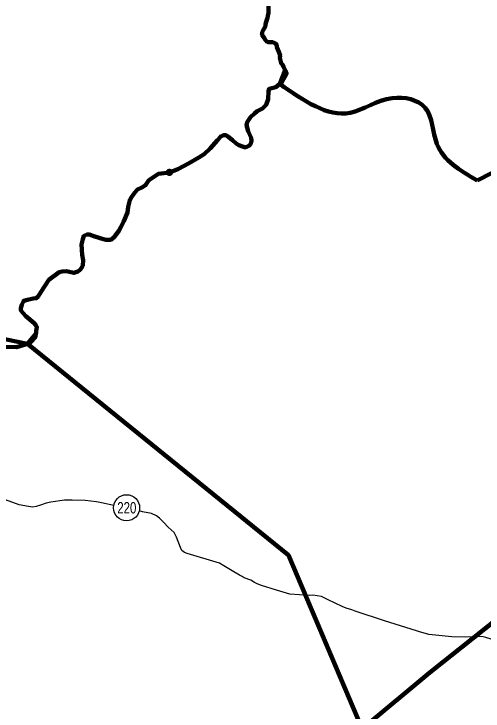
# Model space of a CAD drawing. Extents: x 553962 to 842807, y 8883888 to 9032388.
# Drawn here: x 729677 to 744097, y 8923744 to 8945147 of the extents above; entities that cross this region are included whole.
import ezdxf
from ezdxf.enums import TextEntityAlignment as Align

# ---------------------------------------------------------------- set-up
doc = ezdxf.new("R2010")
doc.units = 0
doc.header["$LTSCALE"] = 200
doc.header["$PDMODE"] = 32
doc.header["$PDSIZE"] = 100
for name, color, linetype, lineweight in [('12', 7, 'Continuous', 25), ('24', 7, 'Continuous', 25), ('48', 7, 'Continuous', 25), ('9', 7, 'Continuous', 90)]:
    doc.layers.add(name, color=color, linetype=linetype, lineweight=lineweight)

msp = doc.modelspace()

# ---------------------------------------------------------------- linework, layer by layer
at = {"layer": '12'}
msp.add_line((742048.5, 8926210.1), (741071.5, 8926510.4), dxfattribs=at)
for points in [[(730249.8, 8930002.8), (730122.6, 8930028.5), (729842.6, 8930080), (728682.6, 8930494.7)], [(732746.1, 8930058.5), (732369.6, 8930141.5), (732211.8, 8930172.4), (731870.6, 8930203.6), (731463.1, 8930219.6), (731228.7, 8930220), (730810.8, 8930159.7), (730662.9, 8930124.3), (730494.6, 8930063.5), (730356.9, 8930023), (730249.8, 8930002.8)], [(741071.5, 8926510.4), (740161.8, 8926805.8), (740060.1, 8926851.9), (739892.2, 8926903.1), (739765, 8926949.2), (739337.8, 8927153.8), (739129.4, 8927261.1), (738864.6, 8927302.4), (738747.4, 8927287.3), (738156.6, 8927334.2), (737744.4, 8927452.2), (737286.5, 8927600.7), (737149.1, 8927646.8), (737067.7, 8927687.7), (736955.9, 8927764.3), (736752.4, 8927830.9), (736696.5, 8927876.9), (736610.1, 8927912.7), (736386.4, 8928050.7), (736127.2, 8928198.9), (736000.1, 8928285.7), (735002.7, 8928577.9), (734921.3, 8928613.7), (734840, 8928669.9), (734799.6, 8928766.8), (734673.4, 8929087.9), (734602.6, 8929225.6), (734419.8, 8929388.9), (734272.7, 8929542), (734150.8, 8929664.5), (734054.3, 8929736), (733901.8, 8929807.6), (733626.9, 8929864.1), (733521.6, 8929887.4)], [(745369.8, 8925577.3), (745323, 8925594.1), (744341.2, 8925952.5), (744183.4, 8925998.7), (744096.9, 8926019.2), (743954.3, 8926029.7), (743572.1, 8926010), (743134, 8926021), (742629.9, 8926077.9), (742426.2, 8926098.7), (742115.8, 8926185.9), (742048.5, 8926210.1)]]:
    msp.add_lwpolyline(points, dxfattribs=at)
at = {"layer": '24', "lineweight": 53}
for points in [[(737354.5, 8945706.8), (737394.5, 8945630.5), (737439.8, 8945559), (737475, 8945507.8), (737499.8, 8945416), (737504.6, 8945365.1), (737504, 8945288.7), (737498.2, 8945176.7), (737482.3, 8945090.2), (737466.6, 8945029.2), (737445.8, 8944963.1), (737430.2, 8944902.1), (737414.4, 8944830.9), (737408.9, 8944774.9), (737372.8, 8944698.8), (737342, 8944653.1), (737311, 8944587.1), (737305.5, 8944531.1), (737295.3, 8944521), (737294.5, 8944512.4)], [(737294.5, 8944512.4), (737310.4, 8944496.3), (737340.7, 8944455.3), (737370.9, 8944409.3), (737411.1, 8944342.9), (737446.4, 8944296.8), (737492, 8944276.2), (737558.2, 8944280.9), (737634.4, 8944280.4), (737715.5, 8944239.2), (737755.9, 8944193.1), (737760.6, 8944132), (737785.4, 8944050.3), (737815.4, 8943978.8), (737855.4, 8943871.7), (737854.9, 8943800.4), (737869.6, 8943718.8), (737889.3, 8943632.1), (737934.8, 8943591.1), (737964.9, 8943524.7), (738014.8, 8943418.8), (738014.7, 8943418.2), (738014.8, 8943418.8)], [(738014.8, 8943418.8), (738029.4, 8943395.5), (738053.2, 8943344.5), (738056.5, 8943309.6), (737913.6, 8943047.9), (737725.2, 8942897.3), (737520.8, 8942846.1), (737498.9, 8942773.1), (737491.6, 8942531.9), (737433.2, 8942356.6), (737316.4, 8942239.7), (737155.8, 8942166.6), (737068.3, 8942093.6), (736944.2, 8941976.7), (736849.3, 8941823.2), (736827.4, 8941728.2), (736878.5, 8941552.9), (736966.1, 8941341), (736980.7, 8941253.3), (736958.8, 8941172.9), (736915, 8941107.2), (736790.9, 8941048.7), (736703.3, 8941077.9), (736593.9, 8941114.5), (736506.3, 8941172.9), (736396.8, 8941267.9), (736243.5, 8941392.1), (736192.4, 8941421.4), (736119.4, 8941421.4), (736031.9, 8941384.8), (735929.7, 8941275.2), (735710.7, 8941012.2), (735528.2, 8940844.2), (735360.4, 8940734.6), (735046.5, 8940559.2), (734718.1, 8940383.8), (734455.3, 8940281.6)], [(734455.3, 8940281.6), (734119.6, 8940237.7), (733827.7, 8940040.4), (733725.5, 8939887), (733608.7, 8939813.9), (733477.3, 8939755.5), (733397, 8939660.5), (733294.9, 8939521.7), (733236.5, 8939434), (733185.4, 8939229.4), (733163.5, 8939054.1), (733054, 8938783.7), (732966.4, 8938601.1), (732900.7, 8938484.2), (732754.8, 8938294.2), (732652.6, 8938213.8), (732506.6, 8938213.8), (732360.6, 8938257.7), (732097.9, 8938338), (732003, 8938374.6), (731915.4, 8938374.6), (731827.8, 8938330.7), (731791.3, 8938235.8), (731754.8, 8938067.7), (731769.4, 8937753.5), (731805.9, 8937585.5), (731798.6, 8937424.7), (731776.7, 8937380.9), (731711.1, 8937293.2), (731638.1, 8937242.1), (731521.3, 8937198.2), (731382.6, 8937227.4), (731295, 8937249.4), (731163.7, 8937242.1), (731068.8, 8937220.1), (730754.9, 8936979), (730506.8, 8936606.4), (730419.2, 8936474.9), (730360.8, 8936416.4), (730273.2, 8936409.1), (730098.1, 8936372.6), (729981.3, 8936343.4), (729966.7, 8936328.8), (729922.9, 8936211.9), (729893.7, 8936109.6), (729893.7, 8936043.8), (730039.7, 8935868.4), (730302.4, 8935656.6), (730346.2, 8935590.8), (730382.7, 8935532.3), (730360.8, 8935422.8), (730360.8, 8935364.3), (730331.6, 8935218.2), (730222.1, 8935094), (730163.7, 8935035.5), (729755, 8934911.3), (729163.8, 8934925.9)]]:
    msp.add_lwpolyline(points, dxfattribs=at)
at = {"layer": '48'}
msp.add_circle((733140.5, 8929984.4), 401.3, dxfattribs=at)
at = {"layer": '9'}
for p, q in [((737849.4, 8942996.8), (738014.8, 8943418.8)), ((742465.8, 8924928.2), (760739.9, 8939450.1))]:
    msp.add_line(p, q, dxfattribs=at)
for points in [[(737354.5, 8945706.8), (737394.5, 8945630.5), (737439.8, 8945559), (737475, 8945507.8), (737499.8, 8945416), (737504.6, 8945365.1), (737504, 8945288.7), (737498.2, 8945176.7), (737482.3, 8945090.2), (737466.6, 8945029.2), (737445.8, 8944963.1), (737430.2, 8944902.1), (737414.4, 8944830.9), (737408.9, 8944774.9), (737372.8, 8944698.8), (737342, 8944653.1), (737311, 8944587.1), (737305.5, 8944531.1), (737295.3, 8944521), (737294.5, 8944512.4)], [(737294.5, 8944512.4), (737310.4, 8944496.3), (737340.7, 8944455.3), (737370.9, 8944409.3), (737411.1, 8944342.9), (737446.4, 8944296.8), (737492, 8944276.2), (737558.2, 8944280.9), (737634.4, 8944280.4), (737715.5, 8944239.2), (737755.9, 8944193.1), (737760.6, 8944132), (737785.4, 8944050.3), (737815.4, 8943978.8), (737855.4, 8943871.7), (737854.9, 8943800.4), (737869.6, 8943718.8), (737889.3, 8943632.1), (737934.8, 8943591.1), (737964.9, 8943524.7), (738014.8, 8943418.8), (738014.7, 8943418.2), (738014.8, 8943418.8)], [(760739.9, 8939450.1), (758705.7, 8940260.8), (758249.4, 8940131.7), (757970.6, 8940028.8), (750978.7, 8943631.9), (743914.7, 8940037.6)], [(760739.9, 8939450.1), (758705.7, 8940260.8), (758249.4, 8940131.7), (757970.6, 8940028.8), (750978.7, 8943631.9), (743914.7, 8940037.6)], [(738014.8, 8943418.8), (738029.4, 8943395.5), (738053.2, 8943344.5), (738056.5, 8943309.6), (737913.6, 8943047.9), (737725.2, 8942897.3), (737520.8, 8942846.1), (737498.9, 8942773.1), (737491.6, 8942531.9), (737433.2, 8942356.6), (737316.4, 8942239.7), (737155.8, 8942166.6), (737068.3, 8942093.6), (736944.2, 8941976.7), (736849.3, 8941823.2), (736827.4, 8941728.2), (736878.5, 8941552.9), (736966.1, 8941341), (736980.7, 8941253.3), (736958.8, 8941172.9), (736915, 8941107.2), (736790.9, 8941048.7), (736703.3, 8941077.9), (736593.9, 8941114.5), (736506.3, 8941172.9), (736396.8, 8941267.9), (736243.5, 8941392.1), (736192.4, 8941421.4), (736119.4, 8941421.4), (736031.9, 8941384.8), (735929.7, 8941275.2), (735710.7, 8941012.2), (735528.2, 8940844.2), (735360.4, 8940734.6), (735046.5, 8940559.2), (734718.1, 8940383.8), (734455.3, 8940281.6)], [(738014.8, 8943418.8), (738029.4, 8943395.5), (738053.2, 8943344.5), (738056.5, 8943309.6), (737913.6, 8943047.9), (737725.2, 8942897.3), (737520.8, 8942846.1), (737498.9, 8942773.1), (737491.6, 8942531.9), (737433.2, 8942356.6), (737316.4, 8942239.7), (737155.8, 8942166.6), (737068.3, 8942093.6), (736944.2, 8941976.7), (736849.3, 8941823.2), (736827.4, 8941728.2), (736878.5, 8941552.9), (736966.1, 8941341), (736980.7, 8941253.3), (736958.8, 8941172.9), (736915, 8941107.2), (736790.9, 8941048.7), (736703.3, 8941077.9), (736593.9, 8941114.5), (736506.3, 8941172.9), (736396.8, 8941267.9), (736243.5, 8941392.1), (736192.4, 8941421.4), (736119.4, 8941421.4), (736031.9, 8941384.8), (735929.7, 8941275.2), (735710.7, 8941012.2), (735528.2, 8940844.2), (735360.4, 8940734.6), (735046.5, 8940559.2), (734718.1, 8940383.8), (734455.3, 8940281.6)], [(737849.6, 8942996.8), (737725.2, 8942897.3), (737520.8, 8942846.1), (737498.9, 8942773.1), (737491.6, 8942531.9), (737433.2, 8942356.6), (737316.4, 8942239.7), (737155.8, 8942166.6), (737068.3, 8942093.6), (736944.2, 8941976.7), (736849.3, 8941823.2), (736827.4, 8941728.2), (736878.5, 8941552.9), (736966.1, 8941341), (736980.7, 8941253.3), (736958.8, 8941172.9), (736915, 8941107.2), (736790.9, 8941048.7), (736703.3, 8941077.9), (736593.9, 8941114.5), (736506.3, 8941172.9), (736396.8, 8941267.9), (736243.5, 8941392.1), (736192.4, 8941421.4), (736119.4, 8941421.4), (736031.9, 8941384.8), (735929.7, 8941275.2), (735710.7, 8941012.2), (735528.2, 8940844.2), (735360.4, 8940734.6), (735046.5, 8940559.2), (734718.1, 8940383.8), (734455.3, 8940281.6)], [(734455.3, 8940281.6), (734119.6, 8940237.7), (733827.7, 8940040.4), (733725.5, 8939887), (733608.7, 8939813.9), (733477.3, 8939755.5), (733397, 8939660.5), (733294.9, 8939521.7), (733236.5, 8939434), (733185.4, 8939229.4), (733163.5, 8939054.1), (733054, 8938783.7), (732966.4, 8938601.1), (732900.7, 8938484.2), (732754.8, 8938294.2), (732652.6, 8938213.8), (732506.6, 8938213.8), (732360.6, 8938257.7), (732097.9, 8938338), (732003, 8938374.6), (731915.4, 8938374.6), (731827.8, 8938330.7), (731791.3, 8938235.8), (731754.8, 8938067.7), (731769.4, 8937753.5), (731805.9, 8937585.5), (731798.6, 8937424.7), (731776.7, 8937380.9), (731711.1, 8937293.2), (731638.1, 8937242.1), (731521.3, 8937198.2), (731382.6, 8937227.4), (731295, 8937249.4), (731163.7, 8937242.1), (731068.8, 8937220.1), (730754.9, 8936979), (730506.8, 8936606.4), (730419.2, 8936474.9), (730360.8, 8936416.4), (730273.2, 8936409.1), (730098.1, 8936372.6), (729981.3, 8936343.4), (729966.7, 8936328.8), (729922.9, 8936211.9), (729893.7, 8936109.6), (729893.7, 8936043.8), (730039.7, 8935868.4), (730302.4, 8935656.6), (730346.2, 8935590.8), (730382.7, 8935532.3), (730360.8, 8935422.8), (730360.8, 8935364.3), (730331.6, 8935218.2), (730222.1, 8935094), (730163.7, 8935035.5), (729755, 8934911.3), (729163.8, 8934925.9)], [(734455.3, 8940281.6), (734119.6, 8940237.7), (733827.7, 8940040.4), (733725.5, 8939887), (733608.7, 8939813.9), (733477.3, 8939755.5), (733397, 8939660.5), (733294.9, 8939521.7), (733236.5, 8939434), (733185.4, 8939229.4), (733163.5, 8939054.1), (733054, 8938783.7), (732966.4, 8938601.1), (732900.7, 8938484.2), (732754.8, 8938294.2), (732652.6, 8938213.8), (732506.6, 8938213.8), (732360.6, 8938257.7), (732097.9, 8938338), (732003, 8938374.6), (731915.4, 8938374.6), (731827.8, 8938330.7), (731791.3, 8938235.8), (731754.8, 8938067.7), (731769.4, 8937753.5), (731805.9, 8937585.5), (731798.6, 8937424.7), (731776.7, 8937380.9), (731711.1, 8937293.2), (731638.1, 8937242.1), (731521.3, 8937198.2), (731382.6, 8937227.4), (731295, 8937249.4), (731163.7, 8937242.1), (731068.8, 8937220.1), (730754.9, 8936979), (730506.8, 8936606.4), (730419.2, 8936474.9), (730360.8, 8936416.4), (730273.2, 8936409.1), (730098.1, 8936372.6), (729981.3, 8936343.4), (729966.7, 8936328.8), (729922.9, 8936211.9), (729893.7, 8936109.6), (729893.7, 8936043.8), (730039.7, 8935868.4), (730302.4, 8935656.6), (730346.2, 8935590.8), (730382.7, 8935532.3), (730360.8, 8935422.8), (730360.8, 8935364.3)], [(734455.3, 8940281.6), (734119.6, 8940237.7), (733827.7, 8940040.4), (733725.5, 8939887), (733608.7, 8939813.9), (733477.3, 8939755.5), (733397, 8939660.5), (733294.9, 8939521.7), (733236.5, 8939434), (733185.4, 8939229.4), (733163.5, 8939054.1), (733054, 8938783.7), (732966.4, 8938601.1), (732900.7, 8938484.2), (732754.8, 8938294.2), (732652.6, 8938213.8), (732506.6, 8938213.8), (732360.6, 8938257.7), (732097.9, 8938338), (732003, 8938374.6), (731915.4, 8938374.6), (731827.8, 8938330.7), (731791.3, 8938235.8), (731754.8, 8938067.7), (731769.4, 8937753.5), (731805.9, 8937585.5), (731798.6, 8937424.7), (731776.7, 8937380.9), (731711.1, 8937293.2), (731638.1, 8937242.1), (731521.3, 8937198.2), (731382.6, 8937227.4), (731295, 8937249.4), (731163.7, 8937242.1), (731068.8, 8937220.1), (730754.9, 8936979), (730506.8, 8936606.4), (730419.2, 8936474.9), (730360.8, 8936416.4)], [(760739.9, 8939450.1), (742465.8, 8924928.2), (740378.1, 8923196.1), (741055, 8921600.7)], [(696242, 8937672.8), (702061.8, 8937200.5), (702208.9, 8933124.7), (710319.1, 8936704.6), (716154, 8938115.2), (724825.2, 8936103.1), (730092.7, 8935013.9)], [(730098.1, 8936372.6), (729981.3, 8936343.4), (729966.7, 8936328.8), (729922.9, 8936211.9), (729893.7, 8936109.6)], [(730360.8, 8936416.4), (730273.2, 8936409.1), (730098.1, 8936372.6)], [(729893.7, 8936109.6), (729893.7, 8936043.8), (730039.7, 8935868.4), (730302.4, 8935656.6), (730346.2, 8935590.8), (730382.7, 8935532.3), (730360.8, 8935422.8), (730360.8, 8935364.3), (730331.6, 8935218.2), (730222.1, 8935094), (730163.7, 8935035.5), (730092.7, 8935013.9), (738115.9, 8928527.7), (740378.1, 8923196.1), (742465.8, 8924928.2)], [(730360.8, 8935364.3), (730353.8, 8935329.2), (730092.7, 8935013.9), (738115.9, 8928527.7), (741055, 8921600.7)]]:
    msp.add_lwpolyline(points, dxfattribs=at)
msp.add_lwpolyline([(730092.7, 8935013.9), (730163.7, 8935035.5), (730222.1, 8935094), (730331.6, 8935218.2), (730353.8, 8935329.2)], close=True, dxfattribs=at)
for points in [[(743914.7, 8940037.6), (742675.2, 8941159), (742317.7, 8942267.2), (741308, 8942564.7), (740014, 8942114.2), (737849.4, 8942996.8)], [(743914.7, 8940037.6), (742675.2, 8941159), (742317.7, 8942267.2), (741308, 8942564.7), (740014, 8942114.2), (737849.6, 8942996.8)]]:
    msp.add_spline(points, degree=3, dxfattribs=at)
msp.add_point((734455.3, 8940281.6), dxfattribs=at)

# ---------------------------------------------------------------- texts
at = {"layer": '48', "width": 0.75}
msp.add_text('220', height=350, dxfattribs=at).set_placement((733147.1, 8929811.1), align=Align.CENTER)

doc.saveas('drawing.dxf')
